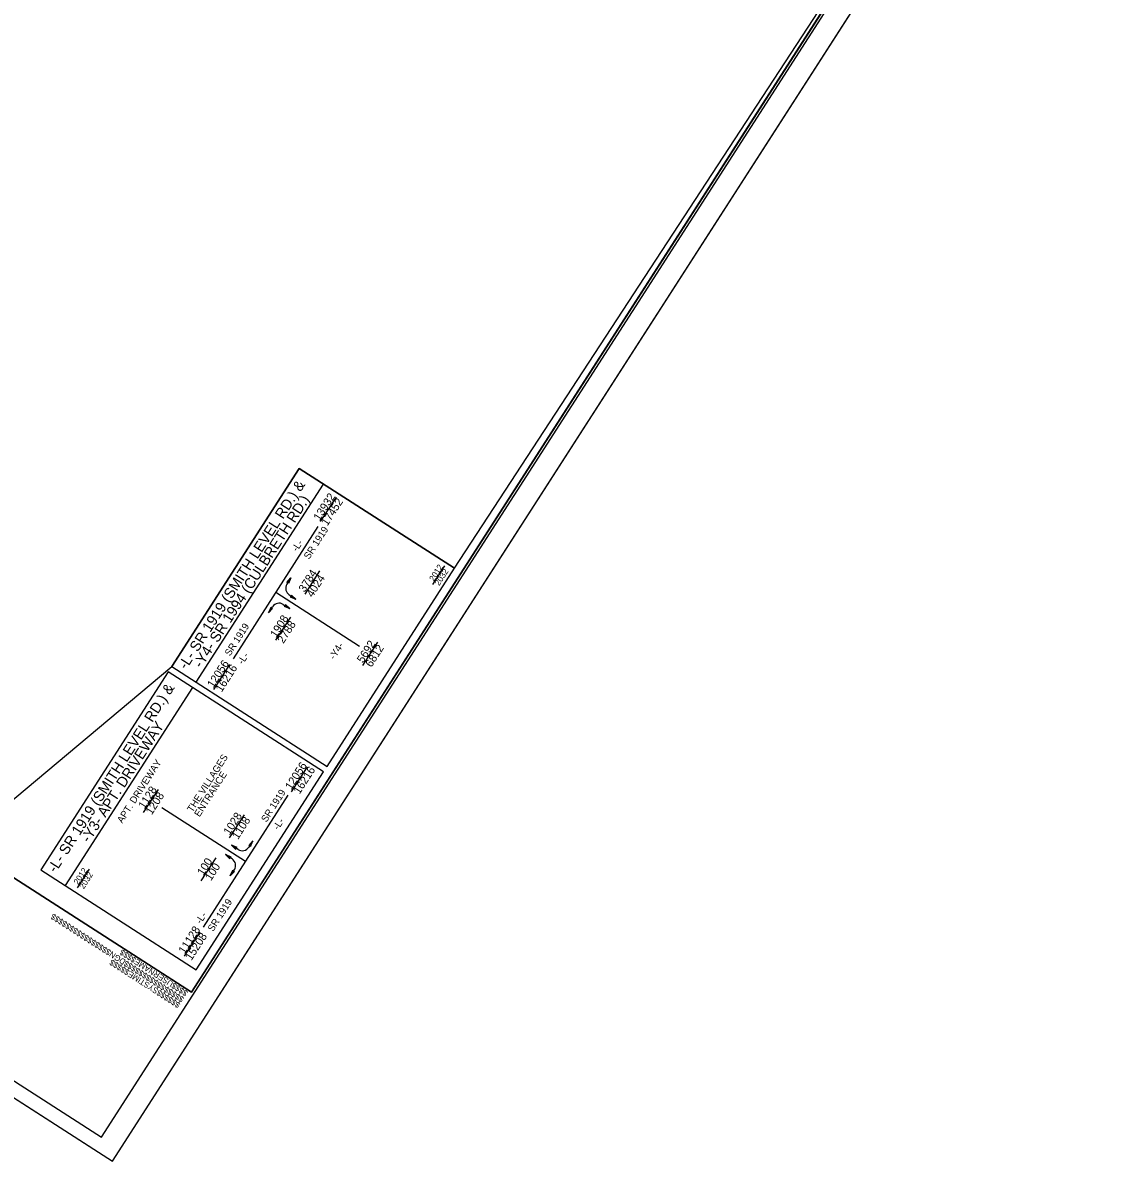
# Model space of a CAD drawing. Extents: x 1976127 to 1977958, y 779377 to 781490.
# Drawn here: x 1976967 to 1977958, y 779386 to 780410 of the extents above; entities that cross this region are included whole.
import ezdxf

# ---------------------------------------------------------------- set-up
doc = ezdxf.new("R2010")
doc.units = 0
for name, color, linetype in [('Prop PHM Label Text', 7, 'Continuous'), ('Prop PHM White Label Box', 7, 'Continuous'), ('Sheet Clip Boundary CELL', 7, 'Continuous'), ('Sheet Cutting Line CELL', 7, 'Continuous'), ('Sheet Plan CELL', 7, 'Continuous'), ('Sheet Plan Layout CELL', 7, 'Continuous'), ('Sheet Plot Border Inside CELL', 7, 'Continuous'), ('Sheet Plot Border Outside CELL', 7, 'Continuous')]:
    doc.layers.add(name, color=color, linetype=linetype)

msp = doc.modelspace()

# ---------------------------------------------------------------- linework, layer by layer
at = {"layer": 'Prop PHM Label Text'}
for p, q in [((1977237.8, 779995), (1977215.7, 780009.2)), ((1977123.2, 779816.8), (1977237.8, 779995)), ((1977235.1, 779961.3), (1977249.3, 779983.3)), ((1977156.7, 779838), (1977233, 779956.8)), ((1977221.1, 779896), (1977234.5, 779916.9)), ((1977336.1, 779904.7), (1977346.9, 779921.6)), ((1977208.4, 779910.6), (1977204.8, 779905)), ((1977270, 779849), (1977194.8, 779897.4)), ((1977206.9, 779895.3), (1977212.9, 779891.5)), ((1977188.1, 779879.1), (1977191.8, 779884.7)), ((1977201.5, 779886.8), (1977207.4, 779883)), ((1977194.9, 779854.6), (1977208.3, 779875.4)), ((1977273.1, 779832), (1977286.5, 779852.8)), ((1977139, 779810.4), (1977153.5, 779832.9)), ((1977005.5, 779633.8), (1977120.1, 779812)), ((1977208.8, 779718.3), (1977223.2, 779740.8)), ((1977075.7, 779699.5), (1977089.1, 779720.4)), ((1977205.6, 779715.1), (1977129.3, 779596.4)), ((1977092.3, 779704.1), (1977167.4, 779655.7)), ((1977153.1, 779676.8), (1977166.5, 779697.6)), ((1977160.8, 779666.3), (1977154.9, 779670.1)), ((1977174.1, 779674.1), (1977170.5, 779668.4)), ((1977127.7, 779638), (1977141.1, 779658.8)), ((1977155.4, 779657.8), (1977149.4, 779661.7)), ((1977016.2, 779631.7), (1977027, 779648.6)), ((1977153.8, 779642.5), (1977157.5, 779648.2)), ((1977112.6, 779570.3), (1977126.8, 779592.3))]:
    msp.add_line(p, q, dxfattribs=at)
for points in [[(1977204.7, 779906.6), (1977208.4, 779910.6), (1977206.3, 779905.5), (1977205.9, 779906.6)], [(1977207.8, 779893.6), (1977212.9, 779891.5), (1977208.8, 779895.2), (1977208.9, 779894)], [(1977202.4, 779885.1), (1977207.4, 779883), (1977203.4, 779886.7), (1977203.4, 779885.6)], [(1977190.3, 779884.1), (1977188.1, 779879.1), (1977191.9, 779883.1), (1977190.7, 779883)], [(1977159.9, 779668), (1977154.9, 779670.1), (1977158.9, 779666.4), (1977158.8, 779667.6)], [(1977172, 779669), (1977174.1, 779674.1), (1977170.4, 779670), (1977171.6, 779670.1)], [(1977154.5, 779659.5), (1977149.4, 779661.7), (1977153.5, 779657.9), (1977153.4, 779659.1)], [(1977157.5, 779646.5), (1977153.8, 779642.5), (1977156, 779647.6), (1977156.4, 779646.5)]]:
    msp.add_lwpolyline(points, close=True, dxfattribs=at)
for centre, start, end in [((1977210.7, 779901.2), 147.255, 237.255), ((1977197.7, 779880.9), 57.255, 147.255), ((1977164.6, 779672.2), 237.255, 327.255), ((1977151.6, 779651.9), 327.255, 57.255)]:
    msp.add_arc(centre, 7, start, end, dxfattribs=at)
at = {"layer": 'Prop PHM White Label Box'}
for points in [[(1977240.9, 779741.1), (1977355.5, 779919.3), (1977215.7, 780009.2), (1977101.1, 779831)], [(1977123.2, 779558.1), (1977237.8, 779736.3), (1977098, 779826.3), (1976983.4, 779648.1)]]:
    msp.add_lwpolyline(points, close=True, dxfattribs=at)
at = {"layer": 'Sheet Clip Boundary CELL'}
msp.add_lwpolyline([(1977101.1, 779831), (1977215.7, 780009.2), (1977355.5, 779919.3), (1977890.2, 780737.4), (1977684.7, 780893.8), (1977248.3, 781047.2), (1977166.5, 781076), (1977126.8, 781101.5), (1977076.7, 781133.9), (1977065, 781118.1), (1976959.9, 781185.7), (1976680, 780774.9), (1976779.9, 780758.8), (1976666.1, 780754.4), (1976646, 780725), (1976307, 780212.9), (1976557, 780088.2), (1976950.5, 779704.7)], close=True, dxfattribs=at)
at = {"layer": 'Sheet Cutting Line CELL'}
for p, q in [((1977047.7, 779385.8), (1977958.3, 780801.7)), ((1976126.7, 779978), (1977047.7, 779385.8))]:
    msp.add_line(p, q, dxfattribs=at)
at = {"layer": 'Sheet Plan CELL'}
msp.add_line((1977118.8, 779538), (1977118.8, 779538), dxfattribs=at)
for points in [[(1977047, 781367.6), (1976235.7, 780105.9), (1977118.8, 779538), (1977930.2, 780799.6)], [(1977118.8, 779538), (1976235.7, 780105.9), (1976938.8, 781199.3), (1977065, 781118.1), (1977173.2, 781286.4), (1977930.2, 780799.6)]]:
    msp.add_lwpolyline(points, close=True, dxfattribs=at)
at = {"layer": 'Sheet Plan Layout CELL'}
msp.add_lwpolyline([(1976235.7, 780105.9), (1977118.8, 779538), (1977930.1, 780799.6), (1977224.9, 781253.1), (1977095.5, 781051.9), (1976917.6, 781166.3)], close=True, dxfattribs=at)
at = {"layer": 'Sheet Plot Border Inside CELL'}
msp.add_lwpolyline([(1977037.9, 779407.5), (1977939, 780808.8), (1977051.7, 781379.4), (1976150.5, 779978.2)], close=True, dxfattribs=at)
at = {"layer": 'Sheet Plot Border Outside CELL'}
msp.add_lwpolyline([(1977047.7, 779385.8), (1977958.3, 780801.7), (1977037.3, 781394), (1976126.7, 779978)], close=True, dxfattribs=at)

# ---------------------------------------------------------------- texts
at = {"layer": 'Prop PHM Label Text'}
for s, height, p in [('-L- SR 1919 (SMITH LEVEL RD.) &', 9.414, (1977114.2, 779827.6)), ('13932', 7.2, (1977234.1, 779961.5)), ('-Y4- SR 1994 (CULBRETH RD.)', 9.414, (1977127.7, 779828.8)), ('17452', 7.2, (1977241.2, 779956.9)), ('SR 1919', 6.28, (1977224.7, 779926.9)), ('-L-', 6.28, (1977213.9, 779933.8)), ('3784', 7.2, (1977220.7, 779897.2)), ('2012', 5.4, (1977336.9, 779907.1)), ('2032', 5.4, (1977341.8, 779903.2)), ('4024', 7.2, (1977227.8, 779892.6)), ('1908', 7.2, (1977195, 779856.3)), ('SR 1919', 6.28, (1977153.5, 779839.8)), ('2788', 7.2, (1977201.6, 779851.1)), ('5692', 7.2, (1977273.2, 779833.5)), ('-Y4-', 6.28, (1977247.5, 779836.7)), ('6812', 7.2, (1977280.8, 779829.7)), ('12056', 7.2, (1977138.5, 779811.2)), ('16216', 7.2, (1977146, 779807.3)), ('-L-', 6.28, (1977165.1, 779832.3)), ('-L- SR 1919 (SMITH LEVEL RD.) &', 9.414, (1976996.6, 779644.7)), ('-Y3- APT. DRIVEWAY', 9.414, (1977026.6, 779671.7)), ('THE VILLAGES', 6.276, (1977119.7, 779699.2)), ('APT. DRIVEWAY', 6.276, (1977056.6, 779689.4)), ('12056', 7.2, (1977208.6, 779719.4)), ('16216', 7.2, (1977216.1, 779715.5)), ('ENTRANCE', 6.28, (1977126.1, 779695.1)), ('1128', 7.2, (1977076.5, 779702.2)), ('1208', 7.2, (1977083.1, 779696.9)), ('SR 1919', 6.28, (1977186.3, 779690.3)), ('1028', 7.2, (1977153.1, 779678.7)), ('1108', 7.2, (1977160.7, 779674.8)), ('-L-', 6.28, (1977197, 779683.4)), ('2012', 5.4, (1977016.9, 779634.1)), ('100', 7.2, (1977129.4, 779642.2)), ('100', 7.2, (1977136.5, 779637.6)), ('2032', 5.4, (1977021.9, 779630.2)), ('SR 1919', 6.28, (1977138.2, 779591.8)), ('-L-', 6.28, (1977127.3, 779598.8)), ('11128', 7.2, (1977112.6, 779571.8)), ('15208', 7.2, (1977118.8, 779565.8))]:
    msp.add_text(s, height=height, rotation=57.2639, dxfattribs=at).set_placement(p)
at = {"layer": 'Sheet Plan CELL'}
for s, p in [('$$$$$$$$$$$$$$$$DGN$$$$$$$$$$$$$$$$', (1977112.7, 779532.8)), ('$$$$$$SYSTIME$$$$$', (1977109.4, 779527.7)), ('$$$$USERNAME$$$$', (1977116.2, 779538.3))]:
    msp.add_text(s, height=5.25, rotation=147.255, dxfattribs=at).set_placement(p)

doc.saveas('drawing.dxf')
